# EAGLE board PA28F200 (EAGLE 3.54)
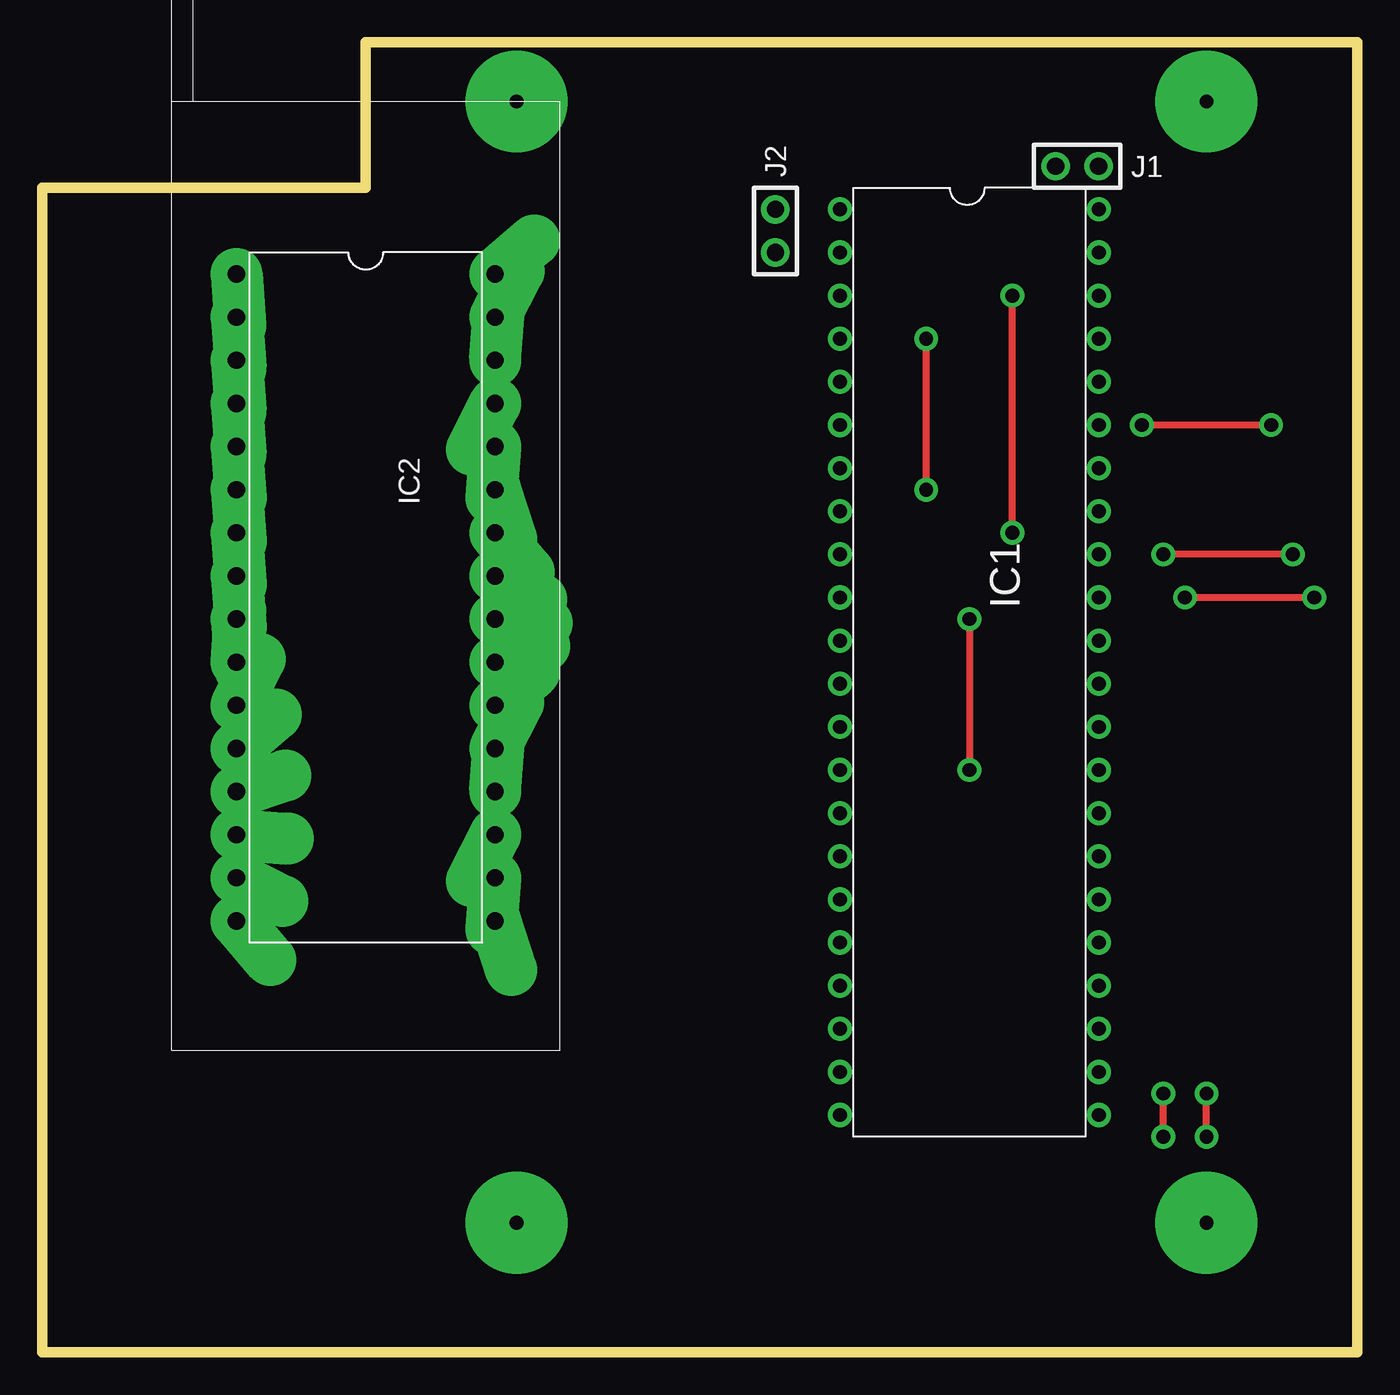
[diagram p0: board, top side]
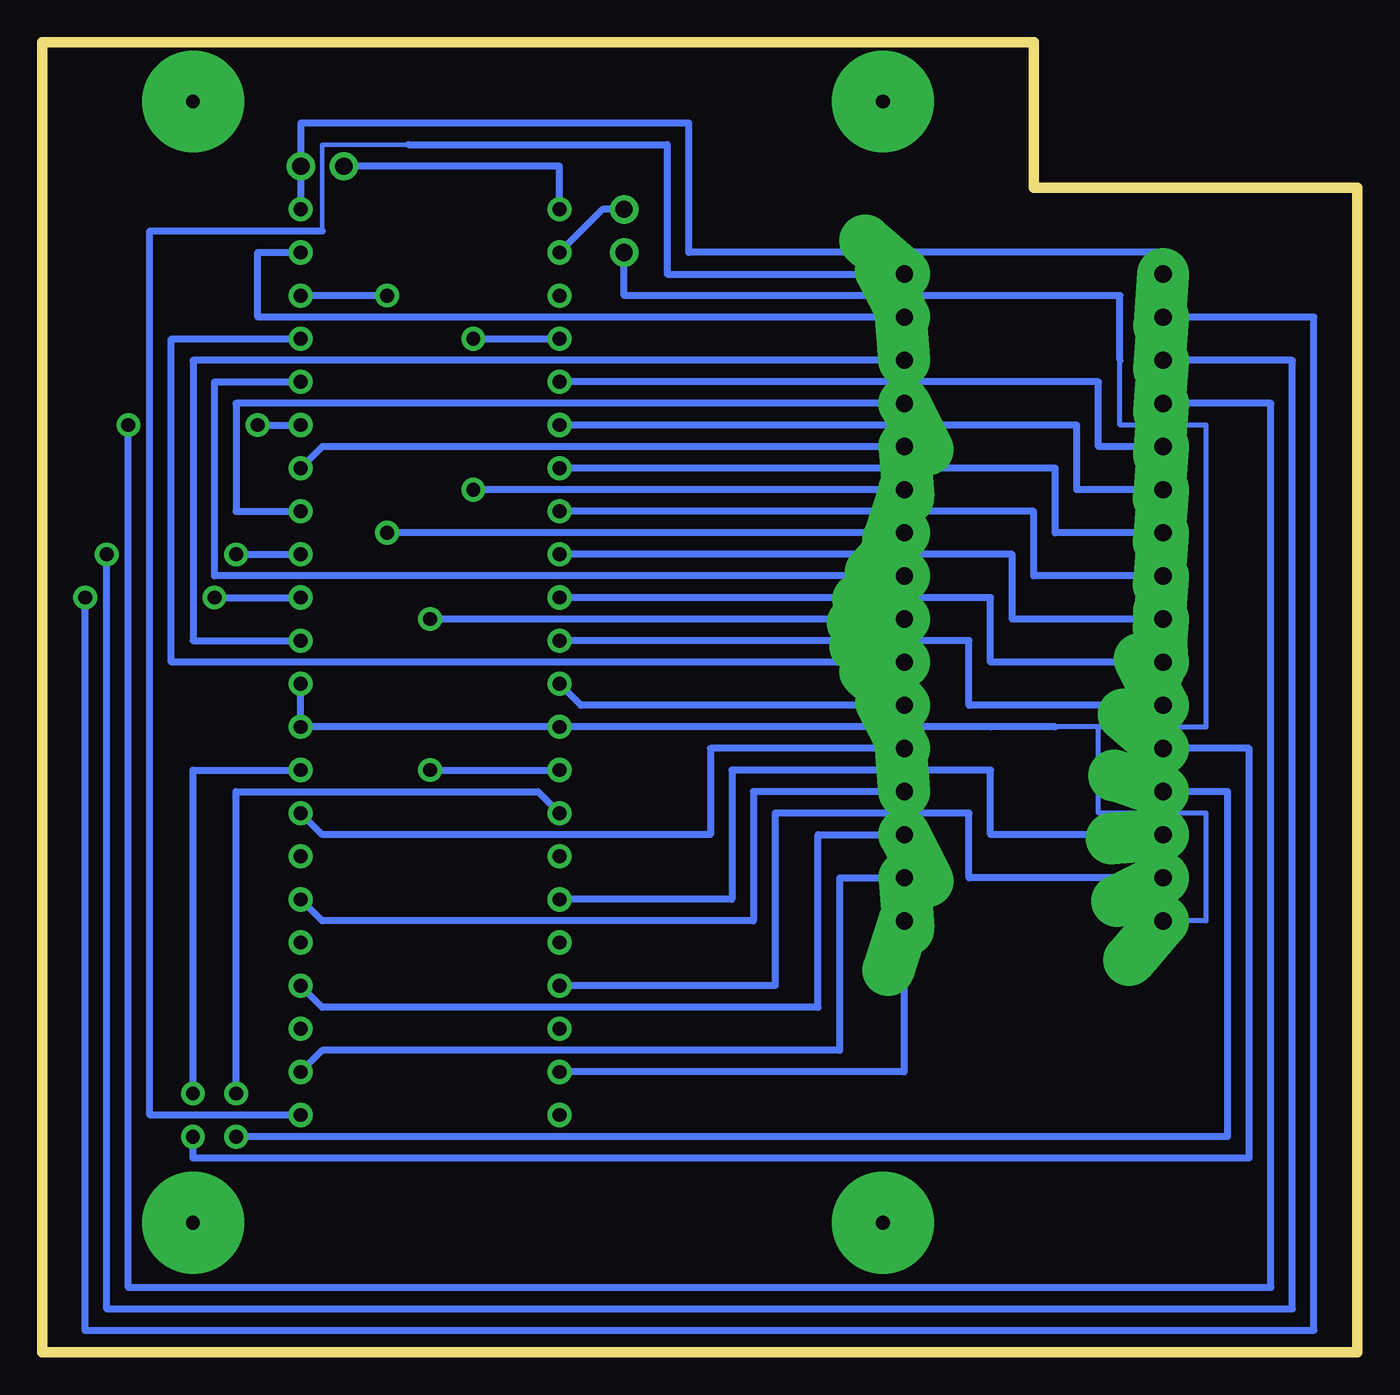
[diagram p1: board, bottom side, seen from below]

Size 77.45 x 77.14 mm. Coordinates in mm from the lower left corner, seen from the top.
Outline: 0,0 77.45,0 77.45,77.14 19.05,77.14 19.05,68.58 0,68.58 0,0
Copper layers used: Top, Bottom

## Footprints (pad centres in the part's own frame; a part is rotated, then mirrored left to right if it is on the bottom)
L-44 = drill 0.813 pad 1.422 round:  -25.4,-7.62;  -22.86,-7.62;  -10.16,-7.62;  -7.62,-7.62;  -20.32,-7.62;  -17.78,-7.62;  -12.7,-7.62;  -15.24,-7.62;  -5.08,-7.62;  -2.54,-7.62;  0,-7.62;  2.54,-7.62;  5.08,-7.62;  7.62,-7.62;  10.16,-7.62;  12.7,-7.62;  15.24,-7.62;  17.78,-7.62;  20.32,-7.62;  22.86,-7.62;  25.4,-7.62;  27.94,-7.62;  27.94,7.62;  25.4,7.62;  22.86,7.62;  20.32,7.62;  17.78,7.62;  15.24,7.62;  12.7,7.62;  10.16,7.62;  7.62,7.62;  5.08,7.62;  2.54,7.62;  0,7.62;  -2.54,7.62;  -5.08,7.62;  -7.62,7.62;  -10.16,7.62;  -12.7,7.62;  -15.24,7.62;  -17.78,7.62;  -20.32,7.62;  -22.86,7.62;  -25.4,7.62
XTO_32 = drill 1.016 pad 3.048 offset:  0,0;  2.54,0;  15.24,0;  17.78,0;  5.08,0;  7.62,0;  12.7,0;  10.16,0;  20.32,0;  22.86,0;  25.4,0;  27.94,0;  30.48,0;  33.02,0;  35.56,0;  38.1,0;  38.1,15.24;  35.56,15.24;  33.02,15.24;  30.48,15.24;  27.94,15.24;  25.4,15.24;  22.86,15.24;  20.32,15.24;  17.78,15.24;  15.24,15.24;  12.7,15.24;  10.16,15.24;  7.62,15.24;  5.08,15.24;  2.54,15.24;  0,15.24
MPER = drill 1.016 pad 1.676 round:  -1.27,0;  1.27,0

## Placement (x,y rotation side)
IC1  P28F200  [L-44]  54.61,41.91 270 top
IC2  TEXTOEP_32  [XTO_32]  11.43,63.5 270 top
J1  JUMPER  [MPER]  60.96,69.85 0 top
J2  JUMPER  [MPER]  43.18,66.04 90 top

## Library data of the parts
IC1 IC2 = galeprom
J1 J2 = holgnorm

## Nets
+5V: IC1. IC2.
A0: IC1. IC2.
A1: IC1. IC2.
A2: IC1. IC2.
A3: IC1. IC2.
A4: IC1. IC2.
A5: IC1. IC2.
A6: IC1. IC2.
A7: IC1. IC2.
A8: IC1. IC2.
A9: IC1. IC2.
A10: IC1. IC2.
A11: IC1. IC2.
A12: IC1. IC2.
A13: IC1. IC2.
A14: IC1. IC2.
A15: IC1. IC2.
A16: IC1. IC2.
A17: IC1. IC2.
CE#: IC1. IC2.
D0: IC1. IC2.
D1: IC1. IC2.
D2: IC1. IC2.
D3: IC1. IC2.
D4: IC1. IC2.
D5: IC1. IC2.
D6: IC1. IC2.
D7: IC1. IC2.
GND: IC1. IC2. J2.
N$3: IC1. J2.
N$5: IC1. J1.
OE#: IC1. IC2.
VPP: IC1. IC2. J1.
WE#: IC1. IC2.

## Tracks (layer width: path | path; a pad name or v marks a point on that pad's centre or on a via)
+5V
  Bottom 0.254: 55.88,71.12 60.96,71.12 60.96,66.04
  Bottom 0.406: IC2. 40.64,63.5 40.64,71.12 55.88,71.12 | 60.96,66.04 71.12,66.04 71.12,13.97 62.23,13.97
A0  (via drill 0.81 pad 1.4)
  Top 0.406: v68.58,12.7 v68.58,15.24
  Bottom 0.406: 62.23,34.29 68.58,34.29 v68.58,15.24 | v68.58,12.7 68.58,11.43 6.35,11.43 6.35,35.56 11.43,35.56
A1
  Bottom 0.406: 11.43,38.1 22.86,38.1 22.86,41.91 46.99,41.91
A2
  Bottom 0.406: 11.43,40.64 21.59,40.64 21.59,44.45 46.99,44.45
A3
  Bottom 0.406: 11.43,43.18 20.32,43.18 20.32,46.99 46.99,46.99
A4
  Bottom 0.406: 11.43,45.72 19.05,45.72 19.05,49.53 46.99,49.53
A5
  Bottom 0.406: 11.43,48.26 17.78,48.26 17.78,52.07 46.99,52.07
A6
  Bottom 0.406: 11.43,50.8 16.51,50.8 16.51,54.61 46.99,54.61
A7
  Bottom 0.406: 11.43,53.34 15.24,53.34 15.24,57.15 46.99,57.15
A8  (via drill 0.81 pad 1.4)
  Top 0.406: v52.07,50.8 v52.07,59.69
  Bottom 0.406: 26.67,50.8 v52.07,50.8 | v52.07,59.69 46.99,59.69
A9  (via drill 0.81 pad 1.4)
  Top 0.406: v57.15,48.26 v57.15,62.23
  Bottom 0.406: 26.67,48.26 v57.15,48.26 | v57.15,62.23 62.23,62.23
A10
  Bottom 0.406: 26.67,40.64 69.85,40.64 69.85,59.69 62.23,59.69
A11
  Bottom 0.406: 26.67,45.72 67.31,45.72 67.31,57.15 62.23,57.15
A12  (via drill 0.81 pad 1.4)
  Top 0.406: v72.39,54.61 v64.77,54.61
  Bottom 0.406: v64.77,54.61 62.23,54.61 | v72.39,54.61 72.39,3.81 5.08,3.81 5.08,55.88 11.43,55.88
A13
  Bottom 0.406: 26.67,53.34 60.96,53.34 62.23,52.07
A14
  Bottom 0.406: 26.67,55.88 66.04,55.88 66.04,49.53 62.23,49.53
A15  (via drill 0.81 pad 1.4)
  Top 0.406: v73.66,46.99 v66.04,46.99
  Bottom 0.406: 11.43,58.42 3.81,58.42 3.81,2.54 73.66,2.54 v73.66,46.99 | v66.04,46.99 62.23,46.99
A16  (via drill 0.81 pad 1.4)
  Top 0.406: v74.93,44.45 v67.31,44.45
  Bottom 0.406: 11.43,60.96 2.54,60.96 2.54,1.27 74.93,1.27 v74.93,44.45 | v67.31,44.45 62.23,44.45
A17
  Bottom 0.406: 26.67,58.42 68.58,58.42 68.58,41.91 62.23,41.91
CE#
  Bottom 0.406: 26.67,38.1 45.72,38.1 46.99,39.37
D0  (via drill 0.81 pad 1.4)
  Top 0.406: v66.04,12.7 v66.04,15.24
  Bottom 0.406: 11.43,33.02 7.62,33.02 7.62,12.7 v66.04,12.7 | v66.04,15.24 66.04,33.02 48.26,33.02 46.99,31.75
D1
  Bottom 0.406: 11.43,30.48 21.59,30.48 21.59,34.29 36.83,34.29 36.83,26.67 46.99,26.67
D2
  Bottom 0.406: 11.43,27.94 22.86,27.94 22.86,31.75 34.29,31.75 34.29,21.59 46.99,21.59
D3
  Bottom 0.406: 26.67,25.4 26.67,16.51 46.99,16.51
D4
  Bottom 0.406: 26.67,27.94 30.48,27.94 30.48,17.78 60.96,17.78 62.23,16.51
D5
  Bottom 0.406: 26.67,30.48 31.75,30.48 31.75,20.32 60.96,20.32 62.23,21.59
D6
  Bottom 0.406: 26.67,33.02 35.56,33.02 35.56,25.4 60.96,25.4 62.23,26.67
D7
  Bottom 0.406: 26.67,35.56 38.1,35.56 38.1,30.48 60.96,30.48 62.23,31.75
GND
  Bottom 0.305: 13.97,58.42 13.97,54.61 8.89,54.61 8.89,36.83 15.24,36.83 | 15.24,36.83 17.78,36.83 | 15.24,36.83 21.59,36.83 | 15.24,36.83 15.24,31.75 8.89,31.75 8.89,25.4 11.43,25.4
  Bottom 0.406: 62.23,39.37 62.23,36.83 46.99,36.83 21.59,36.83 17.78,36.83 | 13.97,58.42 13.97,62.23 43.18,62.23 43.18,64.77
N$3
  Bottom 0.406: 46.99,64.77 44.45,67.31 J2.
N$5
  Bottom 0.406: 46.99,67.31 46.99,69.85 59.69,69.85
N$7  (via drill 0.81 pad 6)
  other vias: 27.94,73.66
N$8  (via drill 0.81 pad 6)
  other vias: 68.58,73.66
N$9  (via drill 0.81 pad 6)
  other vias: 68.58,7.62
N$10  (via drill 0.81 pad 6)
  other vias: 27.94,7.62
OE#  (via drill 0.81 pad 1.4)
  Top 0.406: v54.61,43.18 v54.61,34.29
  Bottom 0.406: 26.67,43.18 v54.61,43.18 | v54.61,34.29 46.99,34.29
VPP
  Bottom 0.406: IC1. J1. 62.23,72.39 39.37,72.39 39.37,64.77 11.43,64.77 11.43,63.5
WE#
  Bottom 0.406: 26.67,60.96 64.77,60.96 64.77,64.77 62.23,64.77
